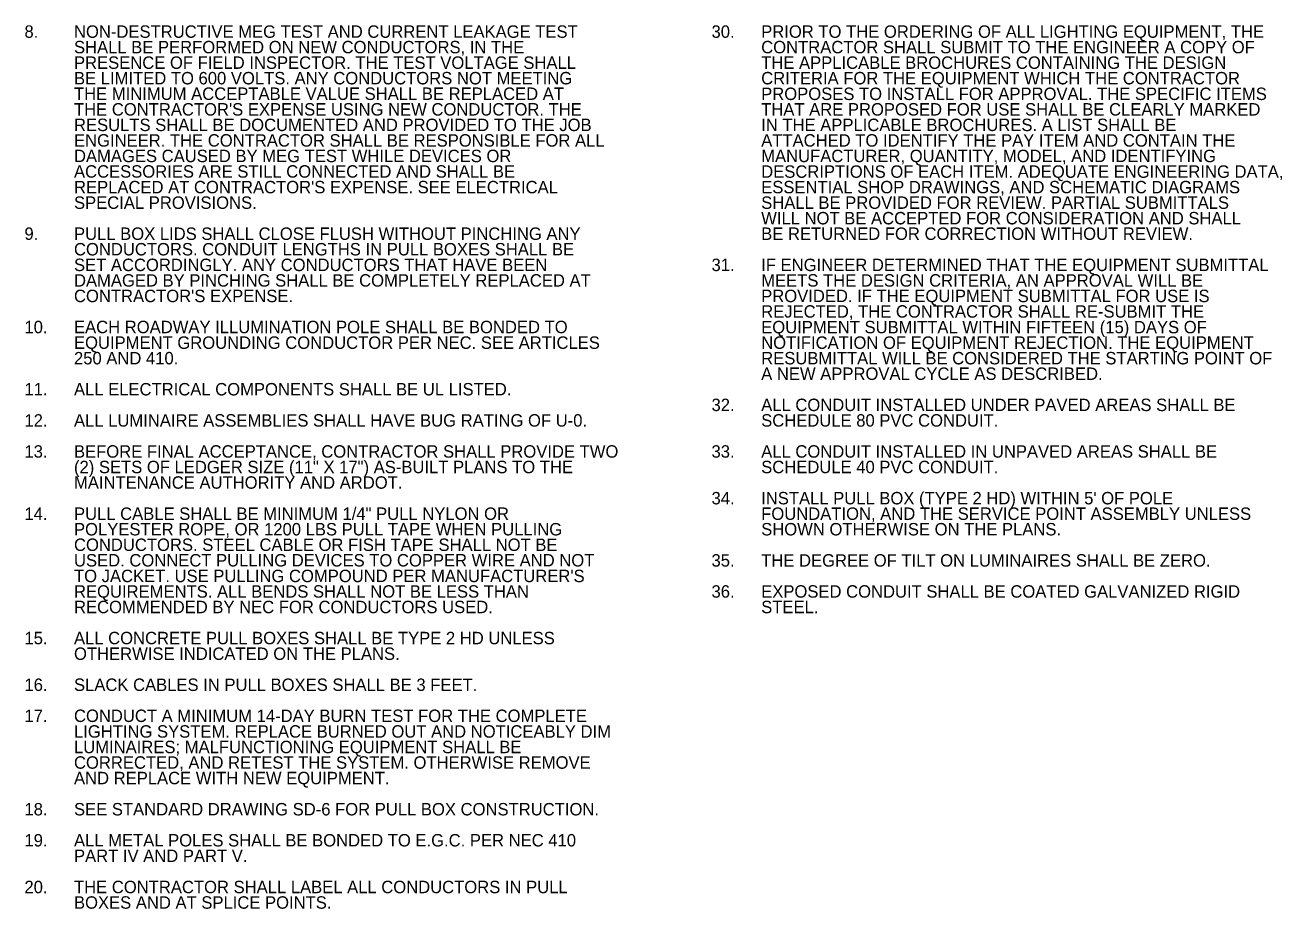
# Model space of a CAD drawing. Extents: x 0.2 to 4.44, y 0.05 to 1.72.
# Drawn here: x 0.201 to 1.213, y 0.25 to 0.962 of the extents above; entities that cross this region are included whole.
import ezdxf

# ---------------------------------------------------------------- set-up
doc = ezdxf.new("R2010")
doc.units = 0
doc.layers.add('E-ANNO-NOTE', color=7, linetype='Continuous')

msp = doc.modelspace()

# ---------------------------------------------------------------- texts
at = {"layer": 'E-ANNO-NOTE'}
for s, p in [('8.', (0.2003, 0.9516)), ('NON-DESTRUCTIVE MEG TEST AND CURRENT LEAKAGE TEST ', (0.2402, 0.9516)), ('30.', (0.7536, 0.9516)), ('PRIOR TO THE ORDERING OF ALL LIGHTING EQUIPMENT, THE ', (0.7936, 0.9516)), ('SHALL BE PERFORMED ON NEW CONDUCTORS, IN THE ', (0.2402, 0.9391)), ('CONTRACTOR SHALL SUBMIT TO THE ENGINEER A COPY OF ', (0.7936, 0.9391)), ('PRESENCE OF FIELD INSPECTOR. THE TEST VOLTAGE SHALL ', (0.2402, 0.9266)), ('THE APPLICABLE BROCHURES CONTAINING THE DESIGN ', (0.7936, 0.9266)), ('BE LIMITED TO 600 VOLTS. ANY CONDUCTORS NOT MEETING ', (0.2402, 0.9141)), ('CRITERIA FOR THE EQUIPMENT WHICH THE CONTRACTOR ', (0.7936, 0.9141)), ('THE MINIMUM ACCEPTABLE VALUE SHALL BE REPLACED AT ', (0.2402, 0.9016)), ('PROPOSES TO INSTALL FOR APPROVAL. THE SPECIFIC ITEMS ', (0.7936, 0.9015)), ("THE CONTRACTOR'S EXPENSE USING NEW CONDUCTOR. THE ", (0.2402, 0.889)), ('THAT ARE PROPOSED FOR USE SHALL BE CLEARLY MARKED ', (0.7936, 0.889)), ('RESULTS SHALL BE DOCUMENTED AND PROVIDED TO THE JOB ', (0.2402, 0.8765)), ('IN THE APPLICABLE BROCHURES. A LIST SHALL BE ', (0.7936, 0.8765)), ('ENGINEER. THE CONTRACTOR SHALL BE RESPONSIBLE FOR ALL ', (0.2402, 0.864)), ('ATTACHED TO IDENTIFY THE PAY ITEM AND CONTAIN THE ', (0.7936, 0.864)), ('DAMAGES CAUSED BY MEG TEST WHILE DEVICES OR ', (0.2402, 0.8515)), ('MANUFACTURER, QUANTITY, MODEL, AND IDENTIFYING ', (0.7936, 0.8515)), ('ACCESSORIES ARE STILL CONNECTED AND SHALL BE ', (0.2402, 0.839)), ('DESCRIPTIONS OF EACH ITEM. ADEQUATE ENGINEERING DATA, ', (0.7936, 0.8389)), ("REPLACED AT CONTRACTOR'S EXPENSE. SEE ELECTRICAL ", (0.2402, 0.8264)), ('ESSENTIAL SHOP DRAWINGS, AND SCHEMATIC DIAGRAMS ', (0.7936, 0.8264)), ('SPECIAL PROVISIONS.', (0.2402, 0.8139)), ('SHALL BE PROVIDED FOR REVIEW. PARTIAL SUBMITTALS ', (0.7936, 0.8139)), ('WILL NOT BE ACCEPTED FOR CONSIDERATION AND SHALL ', (0.7936, 0.8014)), ('9.', (0.2003, 0.7889)), ('PULL BOX LIDS SHALL CLOSE FLUSH WITHOUT PINCHING ANY ', (0.2402, 0.7889)), ('BE RETURNED FOR CORRECTION WITHOUT REVIEW.', (0.7936, 0.7889)), ('CONDUCTORS. CONDUIT LENGTHS IN PULL BOXES SHALL BE ', (0.2402, 0.7764)), ('SET ACCORDINGLY. ANY CONDUCTORS THAT HAVE BEEN ', (0.2402, 0.7638)), ('31.', (0.7536, 0.7638)), ('IF ENGINEER DETERMINED THAT THE EQUIPMENT SUBMITTAL ', (0.7936, 0.7638)), ('DAMAGED BY PINCHING SHALL BE COMPLETELY REPLACED AT ', (0.2402, 0.7513)), ('MEETS THE DESIGN CRITERIA, AN APPROVAL WILL BE ', (0.7936, 0.7513)), ("CONTRACTOR'S EXPENSE.", (0.2402, 0.7388)), ('PROVIDED. IF THE EQUIPMENT SUBMITTAL FOR USE IS ', (0.7936, 0.7388)), ('REJECTED, THE CONTRACTOR SHALL RE-SUBMIT THE ', (0.7936, 0.7263)), ('10.', (0.2003, 0.7138)), ('EACH ROADWAY ILLUMINATION POLE SHALL BE BONDED TO ', (0.2402, 0.7138)), ('EQUIPMENT SUBMITTAL WITHIN FIFTEEN (15) DAYS OF ', (0.7936, 0.7137)), ('EQUIPMENT GROUNDING CONDUCTOR PER NEC. SEE ARTICLES ', (0.2402, 0.7012)), ('NOTIFICATION OF EQUIPMENT REJECTION. THE EQUIPMENT ', (0.7936, 0.7012)), ('250 AND 410.', (0.2402, 0.6887)), ('RESUBMITTAL WILL BE CONSIDERED THE STARTING POINT OF ', (0.7936, 0.6887)), ('A NEW APPROVAL CYCLE AS DESCRIBED.', (0.7936, 0.6762)), ('11.', (0.2003, 0.6637)), ('ALL ELECTRICAL COMPONENTS SHALL BE UL LISTED.', (0.2402, 0.6637)), ('32.', (0.7536, 0.6511)), ('ALL CONDUIT INSTALLED UNDER PAVED AREAS SHALL BE ', (0.7936, 0.6511)), ('12.', (0.2003, 0.6386)), ('ALL LUMINAIRE ASSEMBLIES SHALL HAVE BUG RATING OF U-0.', (0.2402, 0.6386)), ('SCHEDULE 80 PVC CONDUIT.', (0.7936, 0.6386)), ('13.', (0.2003, 0.6136)), ('BEFORE FINAL ACCEPTANCE, CONTRACTOR SHALL PROVIDE TWO ', (0.2402, 0.6136)), ('33.', (0.7536, 0.6136)), ('ALL CONDUIT INSTALLED IN UNPAVED AREAS SHALL BE ', (0.7936, 0.6136)), ('(2) SETS OF LEDGER SIZE (11" X 17") AS-BUILT PLANS TO THE ', (0.2402, 0.6011)), ('SCHEDULE 40 PVC CONDUIT.', (0.7936, 0.6011)), ('MAINTENANCE AUTHORITY AND ARDOT.', (0.2402, 0.5886)), ('34.', (0.7536, 0.576)), ("INSTALL PULL BOX (TYPE 2 HD) WITHIN 5' OF POLE ", (0.7936, 0.576)), ('14.', (0.2003, 0.5635)), ('PULL CABLE SHALL BE MINIMUM 1/4" PULL NYLON OR ', (0.2402, 0.5635)), ('FOUNDATION, AND THE SERVICE POINT ASSEMBLY UNLESS ', (0.7936, 0.5635)), ('POLYESTER ROPE, OR 1200 LBS PULL TAPE WHEN PULLING ', (0.2402, 0.551)), ('SHOWN OTHERWISE ON THE PLANS.', (0.7936, 0.551)), ('CONDUCTORS. STEEL CABLE OR FISH TAPE SHALL NOT BE ', (0.2402, 0.5385)), ('USED. CONNECT PULLING DEVICES TO COPPER WIRE AND NOT ', (0.2402, 0.526)), ('35.', (0.7536, 0.5259)), ('THE DEGREE OF TILT ON LUMINAIRES SHALL BE ZERO.', (0.7936, 0.5259)), ("TO JACKET. USE PULLING COMPOUND PER MANUFACTURER'S ", (0.2402, 0.5134)), ('REQUIREMENTS. ALL BENDS SHALL NOT BE LESS THAN ', (0.2402, 0.5009)), ('36.', (0.7536, 0.5009)), ('EXPOSED CONDUIT SHALL BE COATED GALVANIZED RIGID ', (0.7936, 0.5009)), ('RECOMMENDED BY NEC FOR CONDUCTORS USED.', (0.2402, 0.4884)), ('STEEL.', (0.7936, 0.4884)), ('15.', (0.2003, 0.4634)), ('ALL CONCRETE PULL BOXES SHALL BE TYPE 2 HD UNLESS ', (0.2402, 0.4634)), ('OTHERWISE INDICATED ON THE PLANS.', (0.2402, 0.4508)), ('16.', (0.2003, 0.4258)), ('SLACK CABLES IN PULL BOXES SHALL BE 3 FEET.', (0.2402, 0.4258)), ('17.', (0.2003, 0.4008)), ('CONDUCT A MINIMUM 14-DAY BURN TEST FOR THE COMPLETE ', (0.2402, 0.4008)), ('LIGHTING SYSTEM. REPLACE BURNED OUT AND NOTICEABLY DIM ', (0.2402, 0.3882)), ('LUMINAIRES; MALFUNCTIONING EQUIPMENT SHALL BE ', (0.2402, 0.3757)), ('CORRECTED, AND RETEST THE SYSTEM. OTHERWISE REMOVE ', (0.2402, 0.3632)), ('AND REPLACE WITH NEW EQUIPMENT.', (0.2402, 0.3507)), ('18.', (0.2003, 0.3256)), ('SEE STANDARD DRAWING SD-6 FOR PULL BOX CONSTRUCTION.', (0.2402, 0.3256)), ('19.', (0.2003, 0.3006)), ('ALL METAL POLES SHALL BE BONDED TO E.G.C. PER NEC 410 ', (0.2402, 0.3006)), ('PART IV AND PART V.', (0.2402, 0.2881)), ('20.', (0.2003, 0.263)), ('THE CONTRACTOR SHALL LABEL ALL CONDUCTORS IN PULL ', (0.2402, 0.263)), ('BOXES AND AT SPLICE POINTS.', (0.2402, 0.2505))]:
    msp.add_text(s, height=0.01, rotation=360, dxfattribs=at).set_placement(p)

doc.saveas('drawing.dxf')
